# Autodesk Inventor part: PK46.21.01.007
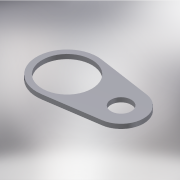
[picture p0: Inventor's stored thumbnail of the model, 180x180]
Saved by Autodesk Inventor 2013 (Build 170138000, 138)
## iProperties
Created: 2005-04
Part Number: PK46.21.01.007
Material: Steel, Mild
Document SubType Name: Modeling
Designer: salex
Manufacturer: Standard
Standards Organization: Custom
Density: 7.86 g/cm^3
Author: salex
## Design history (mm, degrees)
sketch "Эскиз1"
  geometry: L1 (19.688, 133.557)-(254.583, 98.931); L2 (19.688, -133.557)-(254.583, -98.931); C1 r 110.5 at (0, 0); C2 r 45 at (240, 0); A1 r 135 centre (0, 0) between (19.688, 133.557) and (19.688, -133.557); A2 r 100 centre (240, 0) between (254.583, -98.931) and (254.583, 98.931)
  constraints: 4 centre point, 4 end point, 4 point on circle, 4 tangent, 2 coincident, 1 other
  dimensions: "d0" = 221 diameter of C1; "d1" = 0 vertical distance of C2.centre C1.centre; "d2" = 240 distance of C2.centre C1.centre; "d3" = 135 radius of A1; "d4" = 100 radius of A2; "d5" = 90 diameter of C2
extrude "Выдавливание1" new body sketch "Эскиз1" distance "d6" = 20; taper "d7" = 0 deg
body "Solid1"
